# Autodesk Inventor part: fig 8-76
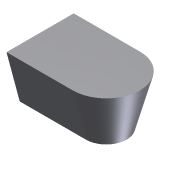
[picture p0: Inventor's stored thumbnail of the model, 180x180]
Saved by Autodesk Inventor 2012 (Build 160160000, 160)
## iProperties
Shininess: 77.0
Length Units: 11269
Angle Units: 11279
Time Units: 11290
Mass Units: 11283
Length Display Precision: 3
Angle Display Precision: 2
Created: 2002-01
Part Number: fig 8-76
Document SubType Name: Modeling
Designer: ***
Density: 1 g/cm^3
Material: Default
Density: 0.0
Volumn: 0.0
Area: 0.0
PropertySet Name: Model Information
Control State: 0
Master: False
Checked Out: False
Author: ***
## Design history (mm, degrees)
sketch "Sketch2"
  geometry: L1 (-19.86, 19.946)-(-19.86, -14.161); L2 (-19.86, -14.161)-(13.729, -14.161); L3 (13.729, 19.946)-(-19.86, 19.946); A1 r 17.054 centre (13.729, 2.893) between (13.729, -14.161) and (13.729, 19.946)
  constraints: 6 end point, 2 point on circle, 2 tangent, 1 centre point, 1 parallel, 1 perpendicular, 1 vertical
extrude "Extrusion2" new body sketch "Sketch2" distance "d6" = 25; taper "d7" = 0 deg
feature "FaceDraft8" dims angle "d14" = -15 deg
body "Solid1"
